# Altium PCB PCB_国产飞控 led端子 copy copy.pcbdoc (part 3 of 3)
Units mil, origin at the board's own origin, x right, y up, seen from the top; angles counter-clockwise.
Board outline 3467.18 x 2997.13 mil, 4 copper layers (Top Layer, Inner1, Inner2, Bottom Layer), stack 2.757 mil thick; 107 components, 163 nets, 527 pads, 148 vias.
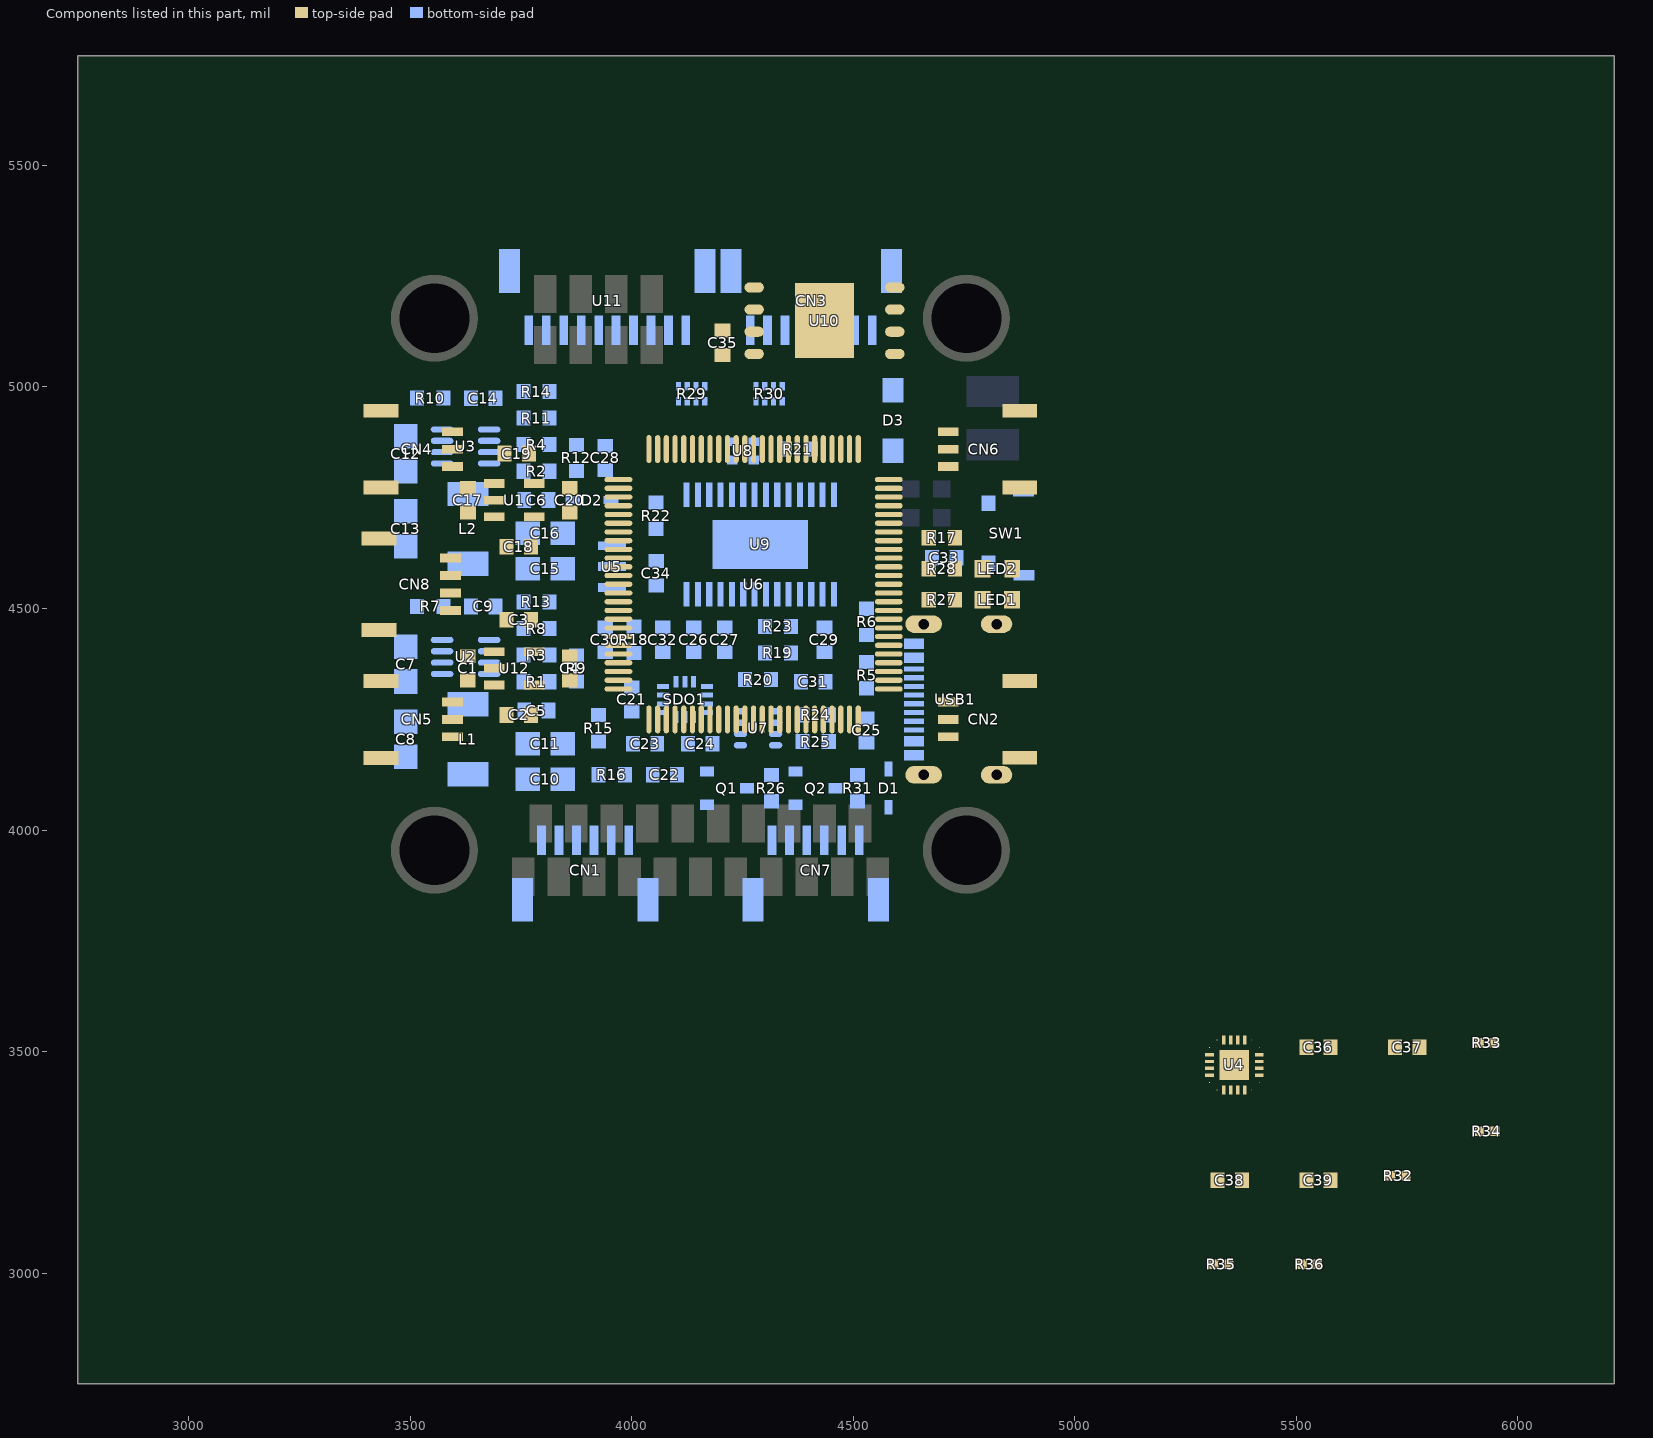
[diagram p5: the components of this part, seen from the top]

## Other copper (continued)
Inner1:
  region net SERVO4: 4245.76,4912.45 4232.82,4925.39 4229.71,4916.42 4236.79,4909.34
  region net SERVO3: 4280.76,4912.45 4267.82,4925.39 4264.71,4916.42 4271.79,4909.34
  region net GYRO_EXTI2: 4052.18,4368.87 4039.24,4381.81 4048.21,4384.92 4055.29,4377.84
  region net GYRO_EXTI2: 4466.93,4420.48 4466.93,4438.78 4458.38,4434.63 4458.38,4424.63
  region net UART3_TX: 3927.18,4068.87 3914.24,4081.81 3923.21,4084.92 3930.29,4077.84
  region net UART3_RX: 4007.18,4068.87 3994.24,4081.81 4003.21,4084.92 4010.29,4077.84
  region net I2C_SCL: 4357.18,4300.39 4344.24,4287.45 4353.21,4284.34 4360.29,4291.42
  region net I2C_SDA: 4297.18,4300.39 4284.24,4287.45 4293.21,4284.34 4300.29,4291.42
  region net I2C_SDA: 4350.76,4106.81 4337.82,4093.87 4334.71,4102.84 4341.79,4109.92
  region net I2C_SCL: 4395.85,4102.7 4414.15,4102.7 4410,4111.25 4400,4111.25
  region net BEEPER: 4463.7,4294.18 4481.16,4299.69 4480,4290.36 4470,4287.21
  region net UART3_RX: 4135.76,4142.45 4122.82,4155.39 4119.71,4146.42 4126.79,4139.34
  region net UART3_TX: 4071.93,4150.48 4071.93,4168.78 4063.38,4164.63 4063.38,4154.63
  region net VBAT: 3797.18,4365.39 3784.24,4352.45 3793.21,4349.34 3800.29,4356.42
  region net VBAT: 3880.88,4275.33 3863.65,4269.12 3864.17,4278.39 3874.57,4282.14
  region net +5V: 4265.76,4461.81 4252.82,4448.87 4249.71,4457.84 4256.79,4464.92
  region net OSD_OUT_VTX: 3825.85,4077.7 3844.15,4077.7 3840,4086.25 3830,4086.25
  region net OSD_OUT_VTX: 4350.76,4352.45 4337.82,4365.39 4334.71,4356.42 4341.79,4349.34
  region net OSD_IN_CAM: 3982.18,4950.39 3969.24,4937.45 3978.21,4934.34 3985.29,4941.42
  region net UART4_TX: 3915.76,4376.81 3902.82,4363.87 3899.71,4372.84 3906.79,4379.92
  region net UART4_TX: 3925.76,4937.45 3912.82,4950.39 3909.71,4941.42 3916.79,4934.34
  region net UART4_RX: 3892.18,4948.87 3879.24,4961.81 3888.21,4964.92 3895.29,4957.84
  region net SERVO4: 4516.93,4605.48 4516.93,4623.78 4508.38,4619.63 4508.38,4609.63
  region net SERVO3: 4630.76,4616.81 4617.82,4603.87 4614.71,4612.84 4621.79,4619.92
  region net LED: 4422.18,4300.39 4409.24,4287.45 4418.21,4284.34 4425.29,4291.42
  region net UART4_RX: 4216.93,4975.48 4216.93,4993.78 4208.38,4989.63 4208.38,4979.63
  region net OSD_IN_CAM: 4055.76,4656.81 4042.82,4643.87 4039.71,4652.84 4046.79,4659.92
  region net VDD: 3975.85,4851.56 3994.15,4851.56 3992.87,4843.01 3977.13,4843.01
  region net VDD: 4565.85,4232.7 4584.15,4232.7 4580,4241.25 4570,4241.25
  region net LED: 4385.85,3907.7 4404.15,3907.7 4400,3916.25 4390,3916.25
  region net LED: 4385.85,3907.7 4404.15,3907.7 4400,3916.25 4390,3916.25
  region net LED: 4785.85,4297.7 4804.15,4297.7 4800,4306.25 4790,4306.25
  region net LED: 4785.85,4281.56 4804.15,4281.56 4800,4273.01 4790,4273.01
  region net LED: 3535.85,4201.56 3554.15,4201.56 3550,4193.01 3540,4193.01
  region net LED: 4807.18,4805.39 4794.24,4792.45 4803.21,4789.34 4810.29,4796.42
  region net +5V: 4112.18,4710.39 4099.24,4697.45 4108.21,4694.34 4115.29,4701.42
  region net +5V: 4725.85,4851.56 4744.15,4851.56 4742.87,4843.01 4727.13,4843.01
  region net +5V: 4725.85,4851.56 4744.15,4851.56 4740,4843.01 4730,4843.01
  region net +5V: 4765.76,4261.81 4752.82,4248.87 4747.68,4255.81 4758.82,4266.95
  region net VDD: 4487.18,4370.39 4474.24,4357.45 4483.21,4354.34 4490.29,4361.42
  region net +5V: 4533.24,4748.93 4520.3,4761.88 4529.28,4764.98 4536.35,4757.91
  region net VDD: 4040.76,4436.81 4027.82,4423.87 4022.68,4430.81 4033.82,4441.95
  region net BEEPER: 4465.85,4152.7 4484.15,4152.7 4480,4161.25 4470,4161.25
Inner2:
  region net SERVO2: 4358.07,4915.48 4358.07,4933.78 4366.62,4929.63 4366.62,4919.63
  region net SERVO1: 4398.07,4955.48 4398.07,4973.78 4406.62,4969.63 4406.62,4959.63
  region net GYRO_EXTI1: 4195.85,4307.7 4214.15,4307.7 4210,4316.25 4200,4316.25
  region net GYRO_EXTI1: 4490.76,4792.45 4477.82,4805.39 4474.71,4796.42 4481.79,4789.34
  region net +10V: 3757.18,4053.87 3744.24,4066.81 3749.43,4070.2 3760.57,4059.06
  region net UART4_RX: 3915.76,4341.81 3902.82,4328.87 3899.71,4337.84 3906.79,4344.92
  region net UART4_RX: 3880.76,4937.45 3867.82,4950.39 3864.71,4941.42 3871.79,4934.34
  region net 3V3-IMU: 3982.18,4265.39 3969.24,4252.45 3978.21,4249.34 3985.29,4256.42
  region net SERVO2: 4537.18,4578.87 4524.24,4591.81 4533.21,4594.92 4540.29,4587.84
  region net SERVO1: 4630.76,4576.81 4617.82,4563.87 4614.71,4572.84 4621.79,4579.92
  region net UART1_RX: 4642.18,4660.39 4629.24,4647.45 4638.21,4644.34 4645.29,4651.42
  region net UART1_TX: 4525.76,4652.45 4512.82,4665.39 4509.71,4656.42 4516.79,4649.34
  region net VBAT_ADC: 4220.76,4126.81 4207.82,4113.87 4206.46,4121.09 4213.54,4128.17
  region net VBAT_ADC: 3962.18,4160.39 3949.24,4147.45 3958.21,4144.34 3965.29,4151.42
  region net CURRENT1: 4260.76,4176.81 4247.82,4163.87 4244.71,4172.84 4251.79,4179.92
  region net CURRENT1: 3798.07,5015.48 3798.07,5033.78 3806.62,5029.63 3806.62,5019.63
  region net +10V: 3748.07,5170.48 3748.07,5188.78 3755,5187.5 3755,5171.76
  region net VDD: 4690.85,4772.7 4709.15,4772.7 4705,4781.25 4695,4781.25
  region net VDD: 4620.85,5191.56 4639.15,5191.56 4635,5183.01 4625,5183.01
  region net LED: 3535.85,4771.56 3554.15,4771.56 3550,4763.01 3540,4763.01
  region net LED: 3535.85,4217.7 3554.15,4217.7 3550,4226.25 3540,4226.25
  region net +5V: 4035.85,5271.56 4054.15,5271.56 4052.87,5263.01 4037.13,5263.01
  region net +5V: 4090.85,4717.7 4109.15,4717.7 4107.87,4726.25 4092.13,4726.25
  region net +5V: 3655.85,4472.7 3674.15,4472.7 3672.87,4481.25 3657.13,4481.25
  region net +5V: 4530.23,4757.75 4511.93,4757.8 4516.06,4766.33 4526.14,4766.3
  region net +5V: 3713.25,4699.16 3731.55,4699.16 3730.27,4690.61 3714.53,4690.61
  region net 3V3-IMU: 4195.76,4176.81 4182.82,4163.87 4179.71,4172.84 4186.79,4179.92
  region net UART1_RX: 4265.85,4086.56 4284.15,4086.56 4280,4078.01 4270,4078.01
  region net UART1_TX: 4126.74,4011.29 4116.85,4026.69 4126.21,4027.92 4131.75,4019.3
  region net UART1_RX: 4207.18,4013.87 4194.24,4026.81 4203.21,4029.92 4210.29,4022.84
Bottom Layer:
  region net BOX_MOSI: 4433.07,4995.48 4433.07,5013.78 4441.62,5009.63 4441.62,4999.63
  region net BOX_MOSI: 4491.93,4995.48 4491.93,5013.78 4483.38,5009.63 4483.38,4999.63
  region net AT_CS: 4290.71,4793.2 4306.87,4801.8 4307.8,4792.62 4297.8,4787.3
  region net AT_CS: 4307.18,4803.87 4294.24,4816.81 4303.21,4819.92 4310.29,4812.84
  region net AT_SCK: 4415.76,4816.81 4402.82,4803.87 4399.71,4812.84 4406.79,4819.92
  region net AT_MISO: 4388.96,4796.34 4370.65,4796.78 4374.6,4788.14 4384.6,4787.9
  region net AT_MOSI: 4338.33,4795.71 4320.11,4797.48 4323.4,4788.57 4333.4,4787.61
  region net BOOT0: 4787.18,4660.39 4774.24,4647.45 4783.21,4644.34 4790.29,4651.42
  region net MOTOR4: 4095.85,4932.7 4114.15,4932.7 4110,4941.25 4100,4941.25
  region net MOTOR3: 4127.94,4926.48 4143.34,4936.37 4135.32,4941.38 4126.71,4935.84
  region net MOTOR2: 4175.76,4936.81 4162.82,4923.87 4159.71,4932.84 4166.79,4939.92
  region net MOTOR1: 4200.85,4932.7 4219.15,4932.7 4215,4939.63 4205,4939.63
  region net SERVO4: 4257.18,4923.87 4244.24,4936.81 4253.21,4939.92 4260.29,4932.84
  region net SERVO3: 4292.18,4923.87 4279.24,4936.81 4288.21,4939.92 4295.29,4932.84
  region net SERVO2: 4345.51,4935.98 4339.3,4918.75 4332.49,4925.06 4336.24,4935.46
  region net SERVO1: 4381.93,4955.48 4381.93,4973.78 4373.38,4969.63 4373.38,4959.63
  region net GYRO_MOSI: 4198.15,4376.69 4188.26,4361.29 4183.25,4369.31 4188.79,4377.92
  region net GYRO_SCK: 4108.7,4359.18 4126.16,4364.69 4125,4355.36 4115,4352.21
  region net GYRO_CS1: 4078.07,4340.48 4078.07,4358.78 4086.62,4354.63 4086.62,4344.63
  region net GYRO_MISO: 4160.85,4341.56 4179.15,4341.56 4175,4333.01 4165,4333.01
  region net GYRO_EXTI2: 4030.85,4361.56 4049.15,4361.56 4045,4353.01 4035,4353.01
  region net GYRO_EXTI1: 4195.85,4291.56 4214.15,4291.56 4210,4283.01 4200,4283.01
  region net D-: 4455.85,4656.56 4474.15,4656.56 4470,4648.01 4460,4648.01
  region net D+: 4480.85,4706.56 4499.15,4706.56 4495,4698.01 4485,4698.01
  region net BB: 4466.93,4085.48 4466.93,4103.78 4460.25,4099.63 4460.25,4089.63
  region net SBUS: 4167.18,4095.39 4154.24,4082.45 4163.21,4079.34 4170.29,4086.42
  region net SBUS: 4146.93,4085.48 4146.93,4103.78 4138.38,4099.63 4138.38,4089.63
  region net +10V: 3757.18,4055.39 3744.24,4042.45 3751.18,4037.31 3762.32,4048.45
  region net +10V: 3735.85,4062.7 3754.15,4062.7 3752.87,4071.25 3737.13,4071.25
  region net UART3_TX: 3915.76,4057.45 3902.82,4070.39 3899.71,4061.42 3906.79,4054.34
  region net UART3_RX: 3986.93,4060.48 3986.93,4078.78 3980,4074.63 3980,4064.63
  region net I2C_SCL: 4335.85,4291.56 4354.15,4291.56 4350,4283.01 4340,4283.01
  region net I2C_SDA: 4275.85,4291.56 4294.15,4291.56 4290,4283.01 4280,4283.01
  region net U6_37: 4235.85,4307.7 4254.15,4307.7 4250,4316.25 4240,4316.25
  region net VBAT: 3438.07,4890.48 3438.07,4908.78 3446.62,4911.44 3446.62,4887.82
  region net VBAT: 3436.3,4889.18 3418.84,4894.69 3413.19,4887.51 3436.81,4880.06
  region net VBAT: 3438.07,4709.88 3438.07,4728.18 3446.62,4730.84 3446.62,4707.22
  region net VBAT: 3436.3,4708.58 3418.84,4714.09 3413.19,4706.91 3436.81,4699.46
  region net VBAT: 3436.3,4729.48 3418.84,4723.97 3413.19,4731.15 3436.81,4738.6
  region net VBAT: 3437.18,4290.39 3424.24,4277.45 3428.4,4269.53 3445.1,4286.23
  region net VBAT: 3415.85,4297.7 3434.15,4297.7 3436.81,4306.25 3413.19,4306.25
  region net VBAT: 3797.18,4900.33 3784.17,4887.45 3791.09,4882.28 3802.29,4893.36
  region net VBAT: 3797.18,4363.93 3784.17,4376.81 3791.09,4381.98 3802.29,4370.9
  region net VBAT: 3883.07,4255.48 3883.07,4273.78 3891.62,4269.63 3891.62,4259.63
  region net +5V: 4273.07,4440.48 4273.07,4458.78 4281.62,4454.63 4281.62,4444.63
  region net +5V: 4265.76,4461.81 4252.82,4448.87 4249.71,4457.84 4256.79,4464.92
  region net HEXT_OUT: 3909.5,4536.97 3906.41,4555.01 3915.52,4552.43 3917.23,4542.43
  region net HEXT_IN: 3907.18,4628.87 3894.24,4641.81 3903.21,4644.92 3910.29,4637.84
  region net U6_14: 3923.07,4495.48 3923.07,4513.78 3931.62,4509.63 3931.62,4499.63
  region net OSD_OUT_VTX: 4362.18,4363.87 4349.24,4376.81 4356.16,4377.87 4363.24,4370.79
  region net UART4_RX: 3870.85,4957.7 3889.15,4957.7 3885,4966.25 3875,4966.25
  region net 3V3-IMU: 3978.07,4255.48 3978.07,4273.78 3986.62,4269.63 3986.62,4259.63
  region net VBAT_ADC: 3962.19,4160.24 3949.08,4147.46 3958.02,4144.24 3965.18,4151.22
  region net VBAT_ADC: 3950.61,4171.82 3937.83,4158.71 3934.61,4167.65 3941.59,4174.81
  region net CURRENT1: 3790.76,5036.81 3777.82,5023.87 3774.71,5032.84 3781.79,5039.92
  region net SWDCLK: 4667.18,4855.39 4654.24,4842.45 4661.46,4841.09 4668.54,4848.17
  region net +5V: 3900.85,4692.7 3919.15,4692.7 3917.87,4701.25 3902.13,4701.25
  region net UART4_RX: 4215.85,4992.7 4234.15,4992.7 4230,5001.25 4220,5001.25
  region net OSD_IN_CAM: 4045.85,4636.56 4064.15,4636.56 4060,4628.01 4050,4628.01
  region net OSD_IN_CAM: 4045.85,4652.7 4064.15,4652.7 4060,4661.25 4050,4661.25
  region net VDD: 4708.07,4755.48 4708.07,4773.78 4716.62,4769.63 4716.62,4759.63
  region net VDD: 4708.07,4755.48 4708.07,4773.78 4716.62,4769.63 4716.62,4759.63
  region net VDD: 3976.93,4850.48 3976.93,4868.78 3968.38,4864.63 3968.38,4854.63
  region net VDD: 4573.15,4236.69 4563.26,4221.29 4558.25,4229.31 4563.79,4237.92
  region net +5V: 4110.45,4703.33 4104.94,4720.79 4114.27,4719.63 4117.42,4709.63
  region net +5V: 4091.93,4700.48 4091.93,4718.78 4083.38,4716.52 4083.38,4702.74
  region net +5V: 4755.85,4241.56 4774.15,4241.56 4772.87,4233.01 4757.13,4233.01
  region net +5V: 4575.76,4002.45 4562.82,4015.39 4557.68,4008.45 4568.82,3997.31
  region net +5V: 4568.7,4025.08 4586.16,4019.57 4587.87,4027.99 4572.13,4032.96
  region net VDD: 4280.85,4186.56 4299.15,4186.56 4295,4179.63 4285,4179.63
  region net VDD: 4280.85,4202.7 4299.15,4202.7 4295,4211.25 4285,4211.25
  region net VDD: 4283.97,4184.02 4280.22,4201.94 4272.69,4196.23 4274.78,4186.23
  region net VDD: 4466.93,4360.48 4466.93,4378.78 4458.38,4374.63 4458.38,4364.63
  region net +5V: 4530.23,4757.75 4511.93,4757.8 4516.1,4766.33 4526.1,4766.3
  region net 3V3-IMU: 4195.76,4176.81 4182.82,4163.87 4179.71,4172.84 4186.79,4179.92
  region net VDD: 4030.85,4416.56 4049.15,4416.56 4045,4408.01 4035,4408.01
  region net BEEPER: 4487.18,4145.39 4474.24,4132.45 4483.21,4129.34 4490.29,4136.42
  region net UART1_RX: 4266.93,4085.48 4266.93,4103.78 4260.2,4099.63 4260.2,4089.63
  region net UART1_RX: 4287.18,4095.39 4274.24,4082.45 4283.21,4079.34 4290.29,4086.42
  region net UART1_TX: 4105.85,4006.56 4124.15,4006.56 4120,3998.01 4110,3998.01
  region net UART1_RX: 4185.85,4006.56 4204.15,4006.56 4200,3998.01 4190,3998.01
  region net I2C_SCL: 4364.34,4006.78 4346.04,4006.34 4350.39,3997.9 4360.39,3998.14
  region net I2C_SDA: 4283.07,4005.48 4283.07,4023.78 4291.62,4019.63 4291.62,4009.63
  region net VBAT: 4755.94,4955.18 4755.94,5024.08 4714.61,5003.41 4714.61,4975.85
  region net SWDCLK: 4680.31,4706.64 4697.99,4724.32 4682.08,4729.62 4675.01,4722.55
  region net VDD: 4719.69,4777.13 4719.69,4752.13 4720,4759.63 4720,4769.63
  region net VDD: 4719.69,4777.13 4719.69,4752.13 4720,4759.63 4720,4769.63
  region net UART1_TX: 4424.84,3943.09 4444.52,3943.09 4439.7,3928.09 4429.7,3928.09
  region net +5V: 4523.26,3956.84 4523.26,3996.21 4536.9,3984.4 4536.9,3968.66
  region net UART1_RX: 4397.64,3943.09 4385.47,3964.93 4379.01,3945.71 4384.07,3936.63
  region net I2C_SCL: 4365.79,4010.02 4346.1,4010.02 4350,4014.51 4360,4014.63
  region net I2C_SDA: 4306.73,3988.01 4318.58,4010.02 4305.09,4016.61 4300.14,4007.42
  region net R13_2: 3798.78,4497.62 3830.53,4497.62 3822.57,4474 3806.83,4474
  region net VBAT: 3907.99,4275.16 3907.99,4252.13 3892.99,4259.63 3892.99,4269.63
  region net VBAT_ADC: 3937.73,4184.1 3912.73,4184.1 3933.16,4169.1 3947.3,4169.1
  region net VDD: 3987.99,4412.43 3987.99,4387.43 3972.99,4394.93 3972.99,4404.93
  region net VDD: 4022.01,4387.43 4022.01,4412.43 4037.01,4404.93 4037.01,4394.93
  region net U6_14: 3987.99,4460.62 4008.33,4475.16 3990.53,4480.87 3982.28,4474.98
  region net U6_37: 4239.47,4322.62 4257.5,4322.62 4250,4307.62 4240,4307.62
  region net MOTOR4: 4111.38,4957.86 4099.57,4957.86 4100,4942.86 4110,4942.86
  region net MOTOR3: 4131.06,4957.86 4119.25,4957.86 4120.2,4944.43 4130.2,4944.43
  region net MOTOR2: 4150.75,4957.86 4138.94,4957.86 4139.8,4954.83 4149.8,4954.83
  region net MOTOR1: 4170.43,4977.74 4170.43,4957.86 4181.8,4962.83 4181.8,4972.83
  region net R29_8: 4099.57,5011.4 4099.57,4991.52 4084.57,4996.43 4084.57,5006.43
  region net R29_7: 4131.06,5011.4 4119.25,5011.4 4120.2,5014.43 4130.2,5014.43
  region net R29_6: 4150.75,5011.4 4138.94,5011.4 4139.8,5026.4 4149.8,5026.4
  region net R29_5: 4170.43,5011.4 4158.62,5011.4 4159.5,5026.4 4169.5,5026.4
  region net SERVO4: 4286.38,4957.86 4274.57,4965.42 4266.24,4952.94 4274.86,4947.42
  region net SERVO3: 4306.06,4957.86 4294.25,4957.86 4295.2,4944.83 4305.2,4944.83
  region net SERVO2: 4325.75,4957.86 4313.94,4957.86 4314.8,4944.83 4324.8,4944.83
  region net SERVO1: 4345.43,4977.13 4345.43,4957.86 4360.43,4959.63 4360.43,4969.63
  region net R30_8: 4286.38,5011.4 4274.57,5011.4 4275.5,5026.4 4285.5,5026.4
  region net R30_7: 4306.06,5011.4 4294.25,5011.4 4295.2,5024.83 4305.2,5024.83
  region net R30_6: 4325.75,5011.4 4313.94,5011.4 4314.8,5014.43 4324.8,5014.43
  region net R30_5: 4345.43,4991.52 4345.43,5011.4 4360.43,5006.43 4360.43,4996.43
  region net VBAT: 4613.62,4965.38 4613.62,5020.49 4654.96,5006.71 4654.96,4979.15
  region net VBAT: 4613.62,5020.49 4566.38,5020.49 4576.22,5061.83 4603.78,5061.83
  region net GYRO_MISO: 4182.5,4329.67 4157.5,4329.67 4165,4344.67 4175,4344.67
  region net GYRO_EXTI1: 4182.97,4259.59 4182.97,4270.61 4195.5,4270.13 4195.5,4260.13
  region net 3V3-IMU: 4145.19,4241.48 4145.19,4261.75 4160.19,4241.35 4160.19,4227.22
  region net 3V3-IMU: 4057.03,4270.61 4057.03,4259.59 4042.03,4260.13 4042.03,4270.13
  region net GYRO_EXTI2: 4057.03,4290.3 4057.03,4279.28 4054.8,4279.83 4054.8,4289.83
  region net GYRO_CS1: 4094.8,4335.73 4105.82,4347.78 4098.54,4353.17 4091.62,4345.94
  region net GYRO_SCK: 4125.51,4347.78 4114.49,4347.78 4115,4362.78 4125,4362.78
  region net GYRO_MOSI: 4145.19,4347.78 4134.17,4347.78 4134.7,4354.33 4144.7,4354.33
  region net 3V3-IMU: 4014.9,4212.35 3989.9,4212.35 3997.4,4227.35 4007.4,4227.35
  region net 3V3-IMU: 4170.22,4176.91 4195.22,4176.91 4198.54,4168.17 4187.93,4164.63
  region net 3V3-IMU: 4194.68,4212.35 4169.68,4212.35 4160.07,4227.35 4174.23,4227.35
  region net UART1_RX: 4276,4106.13 4276,4082.83 4291,4071.56 4291,4085.7
  region net SBUS: 4157.3,4069.03 4182.3,4069.03 4174.8,4079.83 4164.8,4079.83
  region net Q2_1: 4385.5,4069.03 4385.5,4045.43 4400.5,4052.23 4400.5,4062.23
  region net HEXT_OUT: 3923.5,4557.27 3923.5,4537.59 3908.5,4542.43 3908.5,4552.43
  region net HEXT_IN: 3923.5,4651.67 3923.5,4631.99 3908.5,4636.83 3908.5,4646.83
  region net GND: 4216.45,4844.79 4238.19,4832.45 4244.58,4846.07 4235.56,4851.19
  region net U9_6: 4285.59,4825.1 4263.78,4837.32 4257.33,4823.74 4266.4,4818.66
  region net GND: 4265.92,4866.44 4263.78,4886.13 4250.82,4866.49 4252.21,4853.72
  region net U9_5: 4236.3,4866.44 4214.57,4878.8 4208.18,4865.18 4217.19,4860.05
  region net +5V: 4167.95,4729.27 4181.73,4729.27 4179.8,4724.43 4169.8,4724.43
  region net U9_5: 4232.91,4784.39 4219.13,4784.39 4221,4793.63 4231,4793.63
  region net U9_6: 4258.5,4784.39 4244.72,4784.39 4246.6,4799.39 4256.6,4799.39
  region net AT_CS: 4309.69,4784.39 4295.91,4784.39 4297.8,4796.83 4307.8,4796.83
  region net AT_MOSI: 4335.28,4784.39 4321.5,4784.39 4323.4,4799.39 4333.4,4799.39
  region net AT_SCK: 4360.87,4784.39 4347.09,4784.39 4349,4799.39 4359,4799.39
  region net AT_MISO: 4386.46,4784.39 4372.68,4784.39 4374.6,4799.39 4384.6,4799.39
  region net C26_2: 4167.95,4504.86 4181.73,4504.86 4179.8,4492.03 4169.8,4492.03
  region net C27_2: 4193.54,4504.86 4207.32,4504.86 4205.4,4489.86 4195.4,4489.86
  region net +5V: 4219.13,4504.86 4232.91,4504.86 4231,4493.63 4221,4493.63
  region net U9_22: 4284.1,4559.98 4270.32,4559.98 4272.2,4562.43 4282.2,4562.43
  region net +5V: 4295.91,4504.86 4309.69,4504.86 4307.8,4489.86 4297.8,4489.86
  region net U9_19: 4347.09,4504.86 4360.87,4504.86 4359,4489.86 4349,4489.86
  region net C26_2: 4135.88,4472.94 4157.72,4460.77 4164.18,4474.34 4155.1,4479.4
  region net C27_1: 4157.72,4389.53 4157.72,4414.53 4172.72,4407.03 4172.72,4397.03
  region net C27_2: 4212.9,4472.94 4192.28,4472.94 4195.4,4487.94 4205.4,4487.94
  region net C27_1: 4192.28,4414.53 4192.28,4389.53 4177.28,4397.03 4177.28,4407.03
  region net C27_1: 4227.72,4387.13 4227.72,4412.13 4242.72,4404.63 4242.72,4394.63
  region net OSD_IN_CAM: 4067.5,4622.94 4042.5,4622.94 4050,4637.94 4060,4637.94
  region net U9_22: 4051.01,4567.82 4072.72,4555.42 4079.09,4569.05 4070.09,4574.19
  region net OSD_OUT_VTX: 4347.2,4382.62 4372.2,4382.62 4364.7,4374.33 4354.7,4374.33
  region net C27_1: 4284.47,4387.13 4284.47,4412.13 4269.47,4404.63 4269.47,4394.63
  region net AT_CS: 4353.18,4842.62 4329.47,4850.56 4320.91,4837.61 4331.5,4834.06
  region net +5V: 4420.53,4872.13 4420.53,4847.13 4435.53,4854.63 4435.53,4864.63
  region net OSD_IN_CAM: 4042.5,4664.1 4067.5,4664.1 4060,4649.1 4050,4649.1
  region net +5V: 4315.3,4476.64 4290.3,4476.64 4297.8,4491.64 4307.8,4491.64
  region net +5V: 4284.47,4462.13 4284.47,4442.62 4269.47,4444.63 4269.47,4454.63
  region net U9_19: 4343.78,4476.64 4366.5,4476.64 4359,4491.64 4349,4491.64
  region net VDD: 4327.5,4140.16 4302.5,4140.16 4310,4154.63 4320,4154.63
  region net UART1_RX: 4297.99,4059.14 4297.99,4080.85 4282.99,4093.71 4282.99,4079.57
  region net Q2_1: 4492.99,4069.73 4492.99,4049.1 4477.99,4052.23 4477.99,4062.23
  region net BEEPER: 4492.99,4114.14 4492.99,4139.14 4477.99,4148.71 4477.99,4134.57
  region net +5V: 4571.04,4034.79 4588.96,4034.79 4587.87,4019.63 4572.13,4019.63
  region net +5V: 4581.82,4068.06 4588.96,4034.79 4606.29,4066.59 4602.36,4084.92
  region net VBUS: 4571.04,4154.47 4588.96,4154.47 4587.87,4169.63 4572.13,4169.63
  region net VBAT_ADC: 4031.69,4137.13 4031.69,4112.13 4016.69,4119.63 4016.69,4129.63
  region net VDD: 4547.72,4236.44 4547.72,4259.41 4562.72,4238.98 4562.72,4224.84
  region net VDD: 3957.72,4851.44 3957.72,4872.13 3972.72,4864.63 3972.72,4854.63
  region net VDD: 4425.1,4386.32 4450.1,4386.32 4442.6,4371.32 4432.6,4371.32
  region net VDD: 3957.72,4387.43 3957.72,4412.43 3972.72,4404.93 3972.72,4394.93
  region net VDD: 4450.1,4352.35 4425.1,4352.35 4432.6,4367.35 4442.6,4367.35
  region net VDD: 4425.1,4316.91 4450.1,4316.91 4442.6,4301.91 4432.6,4301.91
  region net VDD: 4052.28,4412.43 4052.28,4387.43 4037.28,4394.93 4037.28,4404.93
  region net VBAT_ADC: 4000.53,4112.13 4000.53,4137.13 4015.53,4129.63 4015.53,4119.63
  region net VBAT_ADC: 3968.78,4121.48 3983.57,4141.64 3969.11,4147.29 3963.13,4139.13
  region net VDD: 4450.1,4276.64 4428.78,4276.64 4432.6,4291.64 4442.6,4291.64
  region net VDD: 4432.2,4242.62 4457.2,4242.62 4449.7,4227.62 4439.7,4227.62
  region net I2C_SCL: 4369.47,4255.53 4369.47,4276.64 4354.47,4273.03 4354.47,4263.03
  region net VDD: 4457.2,4216.64 4432.2,4216.64 4439.7,4231.64 4449.7,4231.64
  region net I2C_SDA: 4369.47,4196.3 4384.01,4216.64 4369.65,4222.35 4363.76,4214.1
  region net U3_2: 3621.69,4992.35 3621.69,4956.91 3598.07,4966.76 3598.07,4982.5
  region net U3_2: 3621.69,4956.91 3653.19,4956.91 3642.87,4933.29 3627.13,4933.29
  region net U3_6: 3741.69,4762.35 3741.69,4726.91 3718.07,4736.76 3718.07,4752.5
  region net C6_1: 3828.31,4762.35 3796.81,4762.35 3804.73,4785.97 3820.47,4785.97
  region net VBAT: 3516.57,4861.25 3516.57,4898.11 3540.2,4886.3 3540.2,4870.55
  region net VBAT: 3463.43,4916.76 3463.43,4870.1 3427.99,4887.82 3427.99,4911.44
  region net VBAT: 3463.43,4746.76 3463.43,4691.25 3430,4707.22 3430,4730.84
  region net R12_2: 3762.76,4616.2 3793.38,4591.46 3802.01,4614.86 3789.69,4624.82
  region net R12_2: 3737.87,4616.2 3737.87,4563.06 3702.44,4577.82 3702.44,4601.44
  region net R12_2: 3872.13,4696.2 3840.32,4696.2 3852.13,4719.83 3867.87,4719.83
  region net R12_2: 3849.84,4643.06 3816.62,4664.17 3807.12,4642.22 3820.73,4633.57
  region net C6_1: 3798.78,4792.62 3830.53,4792.62 3820.47,4769 3804.73,4769
  region net U3_4: 3739.47,4796.03 3764.23,4826.64 3743.27,4832.8 3732.72,4821.07
  region net VBAT: 3798.78,4856.47 3824.08,4886.64 3800.45,4895.22 3790.28,4883.1
  region net U3_3: 3764.23,4852.62 3739.47,4883.23 3733.52,4858.99 3744.07,4847.26
  region net U3_8: 3531.22,4988.03 3506.22,4957.62 3529.75,4949.05 3539.8,4961.27
  region net U3_2: 3590.53,4991.64 3590.53,4957.62 3614.15,4966.76 3614.15,4982.5
  region net R11_2: 3830.53,4946.64 3798.78,4946.64 3806.83,4970.26 3822.57,4970.26
  region net R11_2: 3830.53,4943.23 3805.77,4912.62 3829.19,4904.01 3839.14,4916.32
  region net U3_1: 3764.23,4912.62 3739.47,4943.23 3730.86,4916.32 3740.81,4904.01
  region net R12_2: 3857.99,4794.1 3892.01,4794.1 3882.87,4770.48 3867.13,4770.48
  region net R11_2: 3857.99,4860.4 3888.6,4885.16 3861.69,4893.77 3849.38,4883.82
  region net R11_2: 3798.78,4972.62 3830.53,4972.62 3822.57,4949 3806.83,4949
  region net L1_1: 3649.68,4310.93 3610.32,4310.93 3622.13,4334.55 3637.87,4334.55
  region net L1_1: 3676.26,4255.81 3676.26,4289.31 3699.88,4277.5 3699.88,4261.76
  region net +10V: 3676.26,4098.33 3676.26,4144.16 3711.69,4126.44 3711.69,4102.82
  region net BOOT0: 4817.61,4619.73 4792.61,4619.73 4800.11,4629.52 4810.11,4629.52
  region net VDD: 4789.4,4750.31 4789.4,4725.31 4774.4,4732.81 4774.4,4742.81
  region net VBUS: 4630.1,4200.15 4659.23,4195.32 4667.03,4199.08 4653.17,4206.59
  region net DP: 4613.96,4271 4613.96,4259.19 4598.96,4260.13 4598.96,4270.13
  region net DN: 4659.23,4278.88 4659.23,4290.69 4664.8,4289.83 4664.8,4279.83
  region net DN: 4613.96,4290.69 4613.96,4278.88 4598.96,4279.83 4598.96,4289.83
  region net DP: 4613.96,4310.37 4613.96,4298.56 4605.2,4299.43 4605.2,4309.43
  region net DN: 4659.23,4318.25 4659.23,4330.06 4665.5,4329.13 4665.5,4319.13
  region net VBUS: 4659.23,4393.19 4629.99,4389.11 4654.53,4381.58 4668.57,4388.72
  region net UART3_RX: 3904.84,4010.02 3924.52,4003.68 3933.87,4016.42 3923.17,4019.87
  region net SBUS: 3991.43,4010.02 4003.26,3988 4009.86,4007.42 4004.92,4016.62
  region net UART3_TX: 3885.15,4010.02 3865.47,4010.02 3870.3,4025.02 3880.3,4025.02
  region net +10V: 3786.73,3990.03 3806.42,4010.02 3786.9,4023.87 3775.85,4012.65
  region net UART4_RX: 4296.73,5094.24 4316.42,5094.24 4311.6,5091.23 4301.6,5091.23
  region net R30_8: 4336.1,5094.24 4355.79,5094.24 4350.9,5085.53 4340.9,5085.53
  region net R30_7: 4375.47,5094.24 4395.16,5094.24 4390.3,5084.93 4380.3,5084.93
  region net R30_6: 4414.84,5094.24 4434.53,5094.24 4429.7,5084.33 4419.7,5084.33
  region net R30_5: 4454.21,5094.24 4473.9,5094.24 4469.1,5083.73 4459.1,5083.73
  region net +5V: 3969.84,4735.67 3936.57,4742.81 3919.71,4722.27 3938.04,4718.34
  region net R12_2: 3879.68,4735.67 3850.16,4735.67 3852.13,4712.05 3867.87,4712.05
  region net R12_2: 3855.32,4753.59 3883.43,4753.59 3882.87,4777.21 3867.13,4777.21
  region net U3_6: 3676.3,4730.83 3676.3,4764.31 3699.92,4752.5 3699.92,4736.76
  region net U3_6: 3649.68,4785.93 3610.32,4785.93 3622.13,4809.55 3637.87,4809.55
  region net R12_2: 3676.3,4573.33 3676.3,4619.16 3711.73,4601.44 3711.73,4577.82
  region net L1_1: 3741.69,4287.35 3741.69,4251.91 3718.07,4261.76 3718.07,4277.5
  region net R1_2: 3828.31,4287.35 3796.81,4287.35 3806.83,4310.97 3822.57,4310.97
  region net VBAT: 3516.57,4386.25 3516.57,4423.11 3540.2,4411.3 3540.2,4395.55
  region net VBAT: 3463.43,4441.76 3463.43,4386.25 3435,4402.22 3435,4425.84
  region net VBAT: 3463.43,4271.76 3463.43,4221.68 3427.99,4269.93 3427.99,4303.34
  region net R7_1: 3621.69,4522.35 3621.69,4486.91 3598.07,4496.76 3598.07,4512.5
  region net R7_1: 3621.69,4486.91 3653.19,4486.91 3645.27,4463.29 3629.53,4463.29
  region net +10V: 3762.76,4141.2 3793.38,4116.46 3802.01,4139.86 3789.69,4149.82
  region net +10V: 3737.87,4141.2 3737.87,4088.06 3702.44,4102.82 3702.44,4126.44
  region net +10V: 3864.08,4221.2 3824.71,4221.2 3836.53,4244.83 3852.27,4244.83
  region net +10V: 3849.84,4168.06 3816.62,4189.17 3807.12,4167.22 3820.73,4158.57
  region net R1_2: 3798.78,4317.62 3830.53,4317.62 3822.57,4294 3806.83,4294
  region net R1_1: 3739.47,4321.03 3764.23,4351.64 3743.27,4357.8 3732.72,4346.07
  region net VBAT: 3824.08,4377.62 3798.78,4407.79 3790.28,4381.16 3800.45,4369.04
  region net R3_1: 3764.23,4377.62 3739.47,4408.23 3733.52,4383.99 3744.07,4372.26
  region net D-: 4512.99,4380.62 4533.33,4395.16 4515.53,4400.87 4507.28,4394.98
  region net DN: 4547.01,4332.43 4547.01,4307.43 4549.7,4314.93 4549.7,4324.93
  region net D+: 4542.5,4515.16 4517.5,4515.16 4525,4530.16 4535,4530.16
  region net DP: 4547.01,4438.64 4526.67,4424.1 4544.47,4418.39 4552.72,4424.28
  region net R7_2: 3531.22,4518.03 3506.22,4487.62 3529.75,4479.05 3539.8,4491.27
  region net R7_1: 3590.53,4521.64 3590.53,4487.62 3614.15,4496.76 3614.15,4512.5
  region net R13_2: 3830.53,4471.64 3798.78,4471.64 3806.83,4495.26 3822.57,4495.26
  region net R13_2: 3830.53,4468.23 3805.77,4437.62 3829.19,4429.01 3839.14,4441.32
  region net R8_1: 3764.23,4437.62 3739.47,4468.23 3730.86,4441.32 3740.81,4429.01
  region net +10V: 3888.6,4319.1 3857.99,4343.86 3849.38,4320.44 3861.69,4310.49
  region net R13_2: 3857.99,4385.4 3888.6,4410.16 3861.69,4418.77 3849.38,4408.82
  region net 3V3-IMU: 3982.28,4277.13 3982.28,4252.13 3970,4259.63 3970,4269.63
  region net 3V3-IMU: 4017.72,4252.63 4017.72,4277.63 4032.72,4270.13 4032.72,4260.13
  region net 3V3-IMU: 3989.9,4251.32 4014.9,4251.32 4007.4,4236.32 3997.4,4236.32
  region net R29_8: 3836.73,5094.23 3856.42,5094.23 3851.6,5079.23 3841.6,5079.23
  region net UART4_RX: 3797.36,5094.23 3817.05,5094.23 3812.2,5079.23 3802.2,5079.23
  region net CURRENT1: 3757.99,5094.23 3777.68,5094.23 3772.8,5079.23 3762.8,5079.23
  region net R29_7: 3876.1,5094.23 3895.79,5094.23 3890.9,5079.23 3880.9,5079.23
  region net R29_6: 3915.47,5094.23 3935.16,5094.23 3930.3,5084.33 3920.3,5084.33
  region net R29_5: 3954.84,5094.23 3974.53,5094.23 3969.7,5084.93 3959.7,5084.93
  region net VDD: 4253.24,4198.4 4253.23,4184.07 4268.23,4186.23 4268.24,4196.23
  region net VDD: 4253.23,4235.26 4253.23,4249.6 4267.2,4247.43 4267.2,4237.43
  region net I2C_SCL: 4332.65,4260.86 4332.64,4275.19 4347.64,4273.03 4347.65,4263.03
  region net I2C_SDA: 4332.64,4235.26 4332.64,4249.6 4342.5,4247.43 4342.5,4237.43
  region net I2C_SDA: 4316.78,4235.26 4316.78,4249.6 4301.78,4247.43 4301.78,4237.43
  region net VDD: 4316.78,4209.67 4316.77,4224.01 4301.77,4221.83 4301.78,4211.83
  region net R7_2: 3553.2,4435.92 3590.6,4435.92 3579.77,4448.03 3564.03,4448.03
  region net U3_8: 3553.2,4910.92 3590.6,4910.92 3579.77,4918.03 3564.03,4918.03

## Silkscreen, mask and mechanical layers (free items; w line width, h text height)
Top Silkscreen Layer:
  drawing of 33 lines, arcs and shapes, not listed
  text "10V" at 3835,5029.63 h26.77 r180
  text "CAM" at 3925,5029.63 h26.77 r180
  text "GND" at 4005,5029.63 h26.77 r180
  text "5V" at 4065,5029.63 h26.77 r180
  text "R4" at 3825,4979.63 h26.77 r180
  text "T4" at 3910,4979.63 h26.77 r180
  text "GND" at 4005,4979.63 h26.77 r180
  text "5V" at 4065,4979.63 h26.77 r180
  text "SHEEPFINDER" at 4160,4969.63 h59.05
  text "G 5 L" at 3640,4924.63 h26.77 r270
  text "V1.1   2024.1" at 4225,4904.63 h59.05
  text "G 5 L" at 4670,4804.63 h26.77 r90
  text "MCU" at 3730.31,4784.63 h26.77 r270
  text "BOOT" at 4730,4699.63 h31.5
  text "AT32F435" at 4080,4679.63 h78.74
  text "T" at 3630,4624.63 h26.77 r270
  text "U" at 3660,4609.63 h26.77 r270
  text "A" at 3660,4589.63 h26.77 r270
  text "R" at 3629.61,4585.02 h26.77 r270
  text "R" at 3660,4564.63 h26.77 r270
  text "G" at 3629.22,4545.41 h26.77 r270
  text "T" at 3660,4544.63 h26.77 r270
  text "8" at 3660,4524.63 h26.77 r270
  text "5" at 3629.22,4505.41 h26.77 r270
  text "IMU" at 3734.7,4389.63 h26.77 r270
  text "USB" at 4735,4389.63 h31.5
  text "JLCJLCJLCJLC" at 4085,4329.63 h39.37
  text "G 5 L" at 3640,4289.63 h26.77 r270
  text "G 5 L" at 4670,4199.63 h26.77 r90
  text "VTX" at 3760,4129.63 h26.77
  text "5V" at 3855,4129.63 h26.77
  text "T2" at 3925,4129.63 h26.77
  text "R2" at 4005,4129.63 h26.77
  text "T1" at 4085,4129.63 h26.77
  text "R1" at 4160,4129.63 h26.77
  text "SDA" at 4225,4129.63 h26.77
  text "SCL" at 4315,4129.63 h26.77
  text "GND" at 4400,4129.63 h26.77
  text "5V" at 4500,4129.63 h26.77
  text "10V" at 3725,4079.63 h26.77
  text "GND" at 3800,4079.63 h26.77
  text "T3" at 3890,4079.63 h26.77
  text "R3" at 3965,4079.63 h26.77
  text "GND" at 4035,4079.63 h26.77
  text "5V" at 4125,4079.63 h26.77
  text "SBUS" at 4185,4079.63 h26.77
  text "5V" at 4300,4079.63 h26.77
  text "LED" at 4365,4079.63 h26.77
  text "BB-" at 4445,4079.63 h26.77
  text "BB+" at 4535,4079.63 h26.77
Bottom Silkscreen Layer:
  lines w3.94 net S$244950: 4090,3834.63 4140,3834.63 ; 4170,3914.63 4220,3914.63
  lines w3.94 net S$244954: 4095,3824.63 4090,3824.63 4080,3834.63 4090,3844.63 4095,3844.63 ; 4215,3904.63 4220,3904.63 4230,3914.63 4220,3924.63 4215,3924.63
  lines w3.94 net S$288280: 4600,4799.63 4665,4799.63 4675,4789.63
  lines w3.94 net S$288284: 4600,4674.63 4665,4674.63 4675,4684.63
  lines w3.94 net S$288288: 4605,4744.63 4620,4744.63 4625,4749.63
  lines w3.94 net S$288292: 4605,4729.63 4620,4729.63 4625,4724.63
  lines w31.5: 3397.13,3954.24 3397.13,5155.02 cw(c3554.61,5155.02) 3554.61,5312.5 4755.39,5312.5 cw(c4755.39,5155.02) 4912.87,5155.02 4912.87,3954.24 cw(c4755.39,3954.24) 4755.39,3796.76 3554.61,3796.76 cw(c3554.61,3954.24) 3397.13,3954.24
  text "GND" at 4020,5089.63 h26.77 r90
  text "GND" at 4060,5089.63 h26.77 r90
  text "BAT" at 4100,5089.63 h26.77 r90
  text "BAT" at 4140,5089.63 h26.77 r90
  text "GND" at 4520,5089.63 h26.77 r90
  text "BAT" at 4560,5089.63 h26.77 r90
  text "CC" at 3780,5084.63 h26.77 r90
  text "R4" at 3820,5084.63 h26.77 r90
  text "M4" at 3860,5084.63 h26.77 r90
  text "M3" at 3900,5084.63 h26.77 r90
  text "M2" at 3940,5084.63 h26.77 r90
  text "M1" at 3980,5084.63 h26.77 r90
  text "NC" at 4280,5084.63 h26.77 r90
  text "R4" at 4320,5084.63 h26.77 r90
  text "S4" at 4360,5084.63 h26.77 r90
  text "S3" at 4400,5084.63 h26.77 r90
  text "S2" at 4440,5084.63 h26.77 r90
  text "S1" at 4480,5084.63 h26.77 r90
  text "+" at 4730,4954.63 h70.87
  text "-" at 4735,4899.63 h70.87 r90
  text "3.3" at 4590,4774.63 h26.77
  text "GND" at 4595,4739.63 h26.77
  text "IO" at 4575,4704.63 h26.77
  text "5V" at 3645,4699.63 h26.77 r90
  text "CLK" at 4595,4669.63 h26.77
  text "10V" at 3645,4234.63 h26.77 r90
  text "V" at 3790,4014.63 h26.77
  text "0" at 3805,4014.63 h26.77
  text "1" at 3815,4014.63 h26.77
  text "G" at 3845,4014.63 h26.77
  text "3" at 3875,4014.63 h26.77
  text "T" at 3890,4014.63 h26.77
  text "3" at 3915,4014.63 h26.77
  text "R" at 3930,4014.63 h26.77
  text "G" at 3965,4014.63 h26.77
  text "S" at 3995,4014.63 h26.77
  text "S" at 4015,4014.63 h26.77
  text "D" at 4110,3979.63 h26.77
  text "C" at 4140,3979.63 h26.77
  text "1" at 4160,3979.63 h26.77
  text "R" at 4180,3979.63 h26.77
  text "1" at 4205,3979.63 h26.77
  text "T" at 4225,3979.63 h26.77
  text "G" at 4255,3979.63 h26.77
  text "V" at 4285,3979.63 h26.77
  text "5" at 4300,3979.63 h26.77
  text "GPS" at 4235,3934.63 h26.77
  text "DJI" at 4135,3849.63 h26.77
Mechanical Layer:
  lines w0.1: 3334.12,5333.75 3534.12,5133.75 ccw(c3554.86,5154.77) 3575.88,5175.51 3375.88,5375.51 ccw(c3355.14,5354.49) 3334.12,5333.75 ; 3339.12,3780.51 ccw(c3360.14,3759.77) 3380.88,3738.75 3575.88,3933.75 ccw(c3554.86,3954.49) 3534.12,3975.51 3339.12,3780.51 ; 4734.12,3933.75 4929.12,3738.75 ccw(c4949.86,3759.77) 4970.88,3780.51 4775.88,3975.51 ccw(c4755.14,3954.49) 4734.12,3933.75 ; 4734.12,5175.51 4934.12,5375.51 cw(c4954.86,5354.49) 4975.88,5333.75 4775.88,5133.75 cw(c4755.14,5154.77) 4734.12,5175.51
